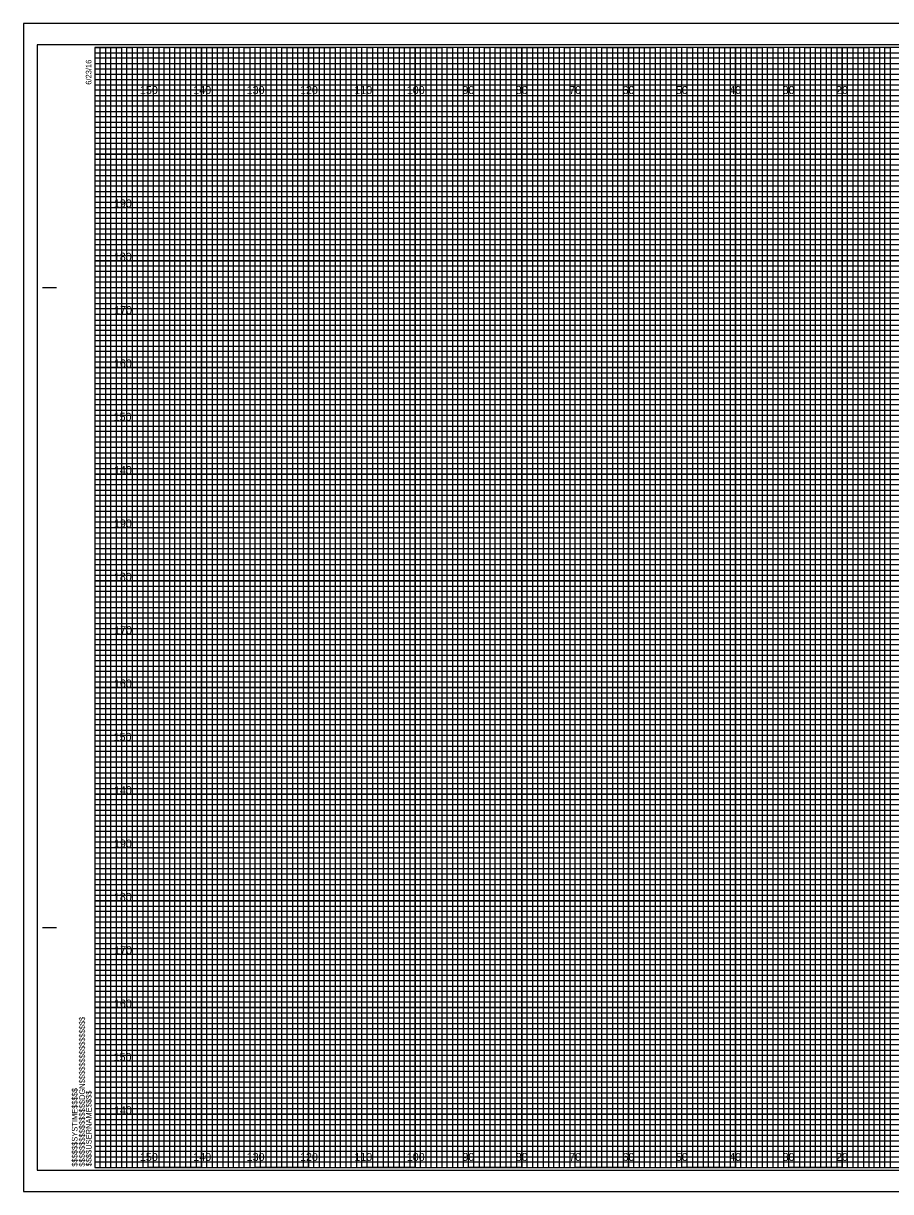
# Model space of a CAD drawing. Extents: x -13 to 323, y -5 to 1754.
# Drawn here: x -13.4 to 149.1, y 215.5 to 434.5 of the extents above; entities that cross this region are included whole.
import ezdxf

# ---------------------------------------------------------------- set-up
doc = ezdxf.new("R2010")
doc.units = 0
for name, color, linetype in [('Exist Cross Section Cell', 7, 'Continuous'), ('Exist XS Center Line Elevation Label', 7, 'Continuous'), ('Exist XS Ground Line', 7, 'Continuous'), ('Prop CMT Pvmt Course 1', 7, 'Continuous'), ('Prop CMT Pvmt Course 2', 7, 'Continuous'), ('Prop CMT Pvmt Course 3', 7, 'Continuous'), ('Prop CMT Shld Paved Course 1', 7, 'Continuous'), ('Prop CMT Shld Paved Course 2', 7, 'Continuous'), ('Prop CMT Subgrade Earthwork', 7, 'Continuous'), ('Prop XS Ditch Standard Text', 7, 'Continuous'), ('Scratch_Level_0', 7, 'Continuous')]:
    doc.layers.add(name, color=color, linetype=linetype)

msp = doc.modelspace()

# ---------------------------------------------------------------- linework, layer by layer
at = {"layer": 'Exist XS Center Line Elevation Label'}
for points in [[(0, 430), (5, 430), (5, 220), (15, 220), (15, 430), (25, 430), (25, 220), (35, 220), (35, 430), (45, 430), (45, 220), (55, 220), (55, 430), (65, 430), (65, 220), (75, 220), (75, 430), (85, 430), (85, 220), (95, 220), (95, 430), (105, 430), (105, 220), (115, 220), (115, 430), (125, 430), (125, 220), (135, 220), (135, 430), (145, 430), (145, 220), (155, 220)], [(0, 425), (275, 425)], [(0, 405), (320, 405), (320, 415), (0, 415)], [(0, 385), (320, 385), (320, 395), (0, 395)], [(0, 365), (320, 365), (320, 375), (0, 375)], [(0, 345), (320, 345), (320, 355), (0, 355)], [(0, 325), (320, 325), (320, 335), (0, 335)], [(0, 305), (320, 305), (320, 315), (0, 315)], [(0, 285), (320, 285), (320, 295), (0, 295)], [(0, 265), (320, 265), (320, 275), (0, 275)], [(0, 245), (320, 245), (320, 255), (0, 255)], [(0, 225), (320, 225), (320, 235), (0, 235)]]:
    msp.add_lwpolyline(points, dxfattribs=at)
at = {"layer": 'Exist XS Ground Line'}
for p, q in [((10, 430), (0, 430)), ((10, 220), (10, 430)), ((30, 430), (20, 430)), ((20, 430), (20, 220)), ((30, 220), (30, 430)), ((50, 430), (40, 430)), ((40, 430), (40, 220)), ((50, 220), (50, 430)), ((70, 430), (60, 430)), ((60, 430), (60, 220)), ((70, 220), (70, 430)), ((90, 430), (80, 430)), ((80, 430), (80, 220)), ((90, 220), (90, 430)), ((110, 430), (100, 430)), ((100, 430), (100, 220)), ((110, 220), (110, 430)), ((130, 430), (120, 430)), ((120, 430), (120, 220)), ((130, 220), (130, 430)), ((150, 430), (140, 430)), ((140, 430), (140, 220)), ((20, 220), (10, 220)), ((40, 220), (30, 220)), ((60, 220), (50, 220)), ((80, 220), (70, 220)), ((100, 220), (90, 220)), ((120, 220), (110, 220)), ((140, 220), (130, 220))]:
    msp.add_line(p, q, dxfattribs=at)
for points in [[(0, 420), (320, 420), (320, 410), (0, 410)], [(0, 400), (320, 400), (320, 390), (0, 390)], [(0, 380), (320, 380), (320, 370), (0, 370)], [(0, 360), (320, 360), (320, 350), (0, 350)], [(0, 340), (320, 340), (320, 330), (0, 330)], [(0, 320), (320, 320), (320, 310), (0, 310)], [(0, 300), (320, 300), (320, 290), (0, 290)], [(0, 280), (320, 280), (320, 270), (0, 270)], [(0, 260), (320, 260), (320, 250), (0, 250)], [(0, 240), (320, 240), (320, 230), (0, 230)]]:
    msp.add_lwpolyline(points, dxfattribs=at)
at = {"layer": 'Prop CMT Pvmt Course 1'}
for p, q in [((323.3, 434.5), (-13.4, 434.5)), ((-13.4, 434.5), (-13.4, 215.5)), ((-13.4, 215.5), (323.3, 215.5))]:
    msp.add_line(p, q, dxfattribs=at)
at = {"layer": 'Prop CMT Pvmt Course 2'}
msp.add_lwpolyline([(-13.4, 215.5), (323.3, 215.5), (323.3, 434.5), (-13.4, 434.5)], close=True, dxfattribs=at)
at = {"layer": 'Prop CMT Pvmt Course 3'}
msp.add_lwpolyline([(-10.8, 219.5), (322.4, 219.5), (322.4, 430.5), (-10.8, 430.5)], close=True, dxfattribs=at)
at = {"layer": 'Prop CMT Shld Paved Course 1'}
for p, q in [((-9.8, 385), (-7.3, 385)), ((-9.7, 385), (-7.2, 385)), ((-9.8, 265), (-7.3, 265)), ((-9.7, 265), (-7.2, 265)), ((0, 220), (0, 220)), ((0, 220), (0, 220)), ((0, 220), (0, 220)), ((0, 220), (0, 220)), ((0, 220), (0, 220)), ((0, 220), (0, 220)), ((0, 220), (0, 220))]:
    msp.add_line(p, q, dxfattribs=at)
msp.add_lwpolyline([(320, 430), (0, 430), (0, 220), (320, 220)], close=True, dxfattribs=at)
at = {"layer": 'Prop CMT Shld Paved Course 2'}
for points in [[(0, 220), (1, 220), (1, 430), (2, 430), (2, 220)], [(2, 220), (3, 220), (3, 430), (4, 430), (4, 220)], [(5, 220), (6, 220), (6, 430), (7, 430), (7, 220)], [(7, 220), (8, 220), (8, 430), (9, 430), (9, 220)], [(10, 220), (11, 220), (11, 430), (12, 430), (12, 220)], [(12, 220), (13, 220), (13, 430), (14, 430), (14, 220)], [(15, 220), (16, 220), (16, 430), (17, 430), (17, 220)], [(17, 220), (18, 220), (18, 430), (19, 430), (19, 220)], [(20, 220), (21, 220), (21, 430), (22, 430), (22, 220)], [(22, 220), (23, 220), (23, 430), (24, 430), (24, 220)], [(25, 220), (26, 220), (26, 430), (27, 430), (27, 220)], [(27, 220), (28, 220), (28, 430), (29, 430), (29, 220)], [(30, 220), (31, 220), (31, 430), (32, 430), (32, 220)], [(32, 220), (33, 220), (33, 430), (34, 430), (34, 220)], [(35, 220), (36, 220), (36, 430), (37, 430), (37, 220)], [(37, 220), (38, 220), (38, 430), (39, 430), (39, 220)], [(40, 220), (41, 220), (41, 430), (42, 430), (42, 220)], [(42, 220), (43, 220), (43, 430), (44, 430), (44, 220)], [(45, 220), (46, 220), (46, 430), (47, 430), (47, 220)], [(47, 220), (48, 220), (48, 430), (49, 430), (49, 220)], [(50, 220), (51, 220), (51, 430), (52, 430), (52, 220)], [(52, 220), (53, 220), (53, 430), (54, 430), (54, 220)], [(55, 220), (56, 220), (56, 430), (57, 430), (57, 220)], [(57, 220), (58, 220), (58, 430), (59, 430), (59, 220)], [(60, 220), (61, 220), (61, 430), (62, 430), (62, 220)], [(62, 220), (63, 220), (63, 430), (64, 430), (64, 220)], [(65, 220), (66, 220), (66, 430), (67, 430), (67, 220)], [(67, 220), (68, 220), (68, 430), (69, 430), (69, 220)], [(70, 220), (71, 220), (71, 430), (72, 430), (72, 220)], [(72, 220), (73, 220), (73, 430), (74, 430), (74, 220)], [(75, 220), (76, 220), (76, 430), (77, 430), (77, 220)], [(77, 220), (78, 220), (78, 430), (79, 430), (79, 220)], [(80, 220), (81, 220), (81, 430), (82, 430), (82, 220)], [(82, 220), (83, 220), (83, 430), (84, 430), (84, 220)], [(85, 220), (86, 220), (86, 430), (87, 430), (87, 220)], [(87, 220), (88, 220), (88, 430), (89, 430), (89, 220)], [(90, 220), (91, 220), (91, 430), (92, 430), (92, 220)], [(92, 220), (93, 220), (93, 430), (94, 430), (94, 220)], [(95, 220), (96, 220), (96, 430), (97, 430), (97, 220)], [(97, 220), (98, 220), (98, 430), (99, 430), (99, 220)], [(100, 220), (101, 220), (101, 430), (102, 430), (102, 220)], [(102, 220), (103, 220), (103, 430), (104, 430), (104, 220)], [(105, 220), (106, 220), (106, 430), (107, 430), (107, 220)], [(107, 220), (108, 220), (108, 430), (109, 430), (109, 220)], [(110, 220), (111, 220), (111, 430), (112, 430), (112, 220)], [(112, 220), (113, 220), (113, 430), (114, 430), (114, 220)], [(115, 220), (116, 220), (116, 430), (117, 430), (117, 220)], [(117, 220), (118, 220), (118, 430), (119, 430), (119, 220)], [(120, 220), (121, 220), (121, 430), (122, 430), (122, 220)], [(122, 220), (123, 220), (123, 430), (124, 430), (124, 220)], [(125, 220), (126, 220), (126, 430), (127, 430), (127, 220)], [(127, 220), (128, 220), (128, 430), (129, 430), (129, 220)], [(130, 220), (131, 220), (131, 430), (132, 430), (132, 220)], [(132, 220), (133, 220), (133, 430), (134, 430), (134, 220)], [(135, 220), (136, 220), (136, 430), (137, 430), (137, 220)], [(137, 220), (138, 220), (138, 430), (139, 430), (139, 220)], [(140, 220), (141, 220), (141, 430), (142, 430), (142, 220)], [(142, 220), (143, 220), (143, 430), (144, 430), (144, 220)], [(145, 220), (146, 220), (146, 430), (147, 430), (147, 220)], [(147, 220), (148, 220), (148, 430), (149, 430), (149, 220)]]:
    msp.add_lwpolyline(points, dxfattribs=at)
at = {"layer": 'Prop CMT Subgrade Earthwork'}
for p, q in [((10, 220), (10, 430)), ((20, 220), (20, 430)), ((30, 220), (30, 430)), ((40, 220), (40, 430)), ((50, 220), (50, 430)), ((60, 220), (60, 430)), ((70, 220), (70, 430)), ((80, 220), (80, 430)), ((90, 220), (90, 430)), ((100, 220), (100, 430)), ((110, 220), (110, 430)), ((120, 220), (120, 430)), ((130, 220), (130, 430)), ((140, 220), (140, 430)), ((0, 420), (320, 420)), ((0, 410), (320, 410)), ((0, 400), (320, 400)), ((0, 390), (320, 390)), ((0, 380), (320, 380)), ((0, 370), (320, 370)), ((0, 360), (320, 360)), ((0, 350), (320, 350)), ((0, 340), (320, 340)), ((0, 330), (320, 330)), ((0, 320), (320, 320)), ((0, 310), (320, 310)), ((0, 300), (320, 300)), ((0, 290), (320, 290)), ((0, 280), (320, 280)), ((0, 270), (320, 270)), ((0, 260), (320, 260)), ((0, 250), (320, 250)), ((0, 240), (320, 240)), ((0, 230), (320, 230))]:
    msp.add_line(p, q, dxfattribs=at)
at = {"layer": 'Scratch_Level_0'}
for p, q in [((0, 429), (260, 429)), ((260, 427.98), (0, 427.98)), ((0, 427.98), (0, 427)), ((0, 427), (260, 427)), ((260, 425.89), (0, 425.89)), ((0, 425.89), (0, 424)), ((0, 424), (320, 424))]:
    msp.add_line(p, q, dxfattribs=at)
for points in [[(0, 423), (270, 423), (320, 423), (320, 422), (0, 422)], [(0, 421), (320, 421), (320, 419), (0, 419)], [(0, 418), (320, 418), (320, 417), (0, 416.98)], [(0, 416), (320, 416), (320, 414), (0, 414)], [(0, 413), (320, 413), (320, 412), (0, 412)], [(0, 411), (320, 411), (320, 409), (0, 409)], [(0, 408), (320, 408), (320, 407), (0, 407)], [(0, 406), (320, 406), (320, 404), (0, 404)], [(0, 403), (320, 403), (320, 402), (0, 402)], [(0, 401), (320, 401), (320, 399), (0, 399)], [(0, 398), (320, 398), (320, 397), (0, 397)], [(0, 396), (320, 396), (320, 393.95), (320, 393), (320, 392), (0, 392)], [(0, 394), (320, 394), (320, 393), (0, 393)], [(0, 391), (320, 391), (320, 389), (0, 389.03)], [(0, 389.03), (320, 389), (320, 388), (0, 388)], [(0, 387), (320, 387), (320, 386), (0, 386)], [(0, 384), (320, 384), (320, 383), (0, 383)], [(0, 382), (320, 382), (320, 381), (0, 381)], [(-0.07, 378.89), (320, 378.89), (320, 377.88), (-0.07, 377.88)], [(0, 377), (320, 377), (320, 376), (0, 376)], [(0, 374), (320, 374), (320, 373), (0, 373)], [(0, 372), (320, 372), (320, 371), (0, 371)], [(0, 369), (320, 369), (320, 368), (0, 368)], [(0, 367), (320, 367), (320, 366), (0, 366)], [(0, 364), (320, 364), (320, 363), (0, 363)], [(0, 362), (320, 362), (320, 361), (0, 361)], [(0, 359), (320, 359), (319.99, 357.98), (0, 358)], [(0, 357), (320, 357), (320, 356), (0, 356)], [(0, 354), (320, 354), (320, 353), (0, 353)], [(0, 352), (320, 352), (320, 351), (0, 351)], [(0, 349), (320, 349), (320, 348), (0, 348)], [(0, 347), (320, 347), (320, 346), (0, 346)], [(0, 344), (320, 344), (320, 343), (0, 343)], [(0, 342), (320, 342), (320, 341), (0, 341)], [(0, 339), (320, 339), (320, 338), (0, 338)], [(0, 336.99), (320.07, 336.91), (320, 336), (0, 336)], [(0, 334), (320, 334), (320, 333), (0, 333)], [(0, 332), (320, 332), (320, 331), (0, 331)], [(0, 329), (320, 329), (320, 328), (0, 328)], [(0, 327), (320, 327), (320, 326), (0, 326)], [(0, 324), (320, 324), (320, 323), (0, 323)], [(0, 322), (320, 322), (320, 321), (0, 321)], [(0, 319), (320, 319), (320, 318), (0, 318)], [(0, 317), (320, 317), (320, 316), (0, 316)], [(0, 314), (320, 314), (320, 313), (0, 313)], [(0, 312), (320, 312), (320, 311), (0, 311)], [(0, 309), (320, 309), (320, 308), (0, 308)], [(0, 307), (320, 307), (320, 306), (0, 306)], [(0, 304), (320, 304), (320, 303), (0, 303)], [(0, 302), (320, 302), (320, 301), (0, 301)], [(0, 299), (320, 299), (319.99, 297.98), (0, 298)], [(0, 297), (320, 297), (320, 296), (0, 296)], [(0, 294), (320, 294), (320, 293), (0, 293)], [(0, 292), (320, 292), (320, 291), (0, 291)], [(0, 289), (320, 289), (320, 288), (0, 288)], [(0, 287), (320, 287), (320, 286), (0, 286)], [(0, 284), (320, 284), (320, 283), (0, 283)], [(0, 282), (320, 282), (320, 281), (0, 281)], [(0, 279), (320, 279), (320, 278), (0, 278)], [(0, 276.99), (320.07, 276.91), (320, 276), (0, 276)], [(0, 274), (320, 274), (320, 273), (0, 273)], [(0, 272), (320, 272), (320, 271), (0, 271)], [(0, 269), (320, 269), (320, 268), (0, 268)], [(0, 267), (320, 267), (320, 266), (0, 266)], [(0, 264), (320, 264), (320, 263), (0, 263)], [(0, 262), (320, 262), (320, 261), (0, 261)], [(0, 259), (320, 259), (320, 258), (0, 258)], [(0, 257), (320, 257), (320, 256), (0, 256)], [(0, 254), (320, 254), (320, 253), (0, 253)], [(0, 252), (320, 252), (320, 251), (0, 251)], [(0, 249), (320, 249), (320, 248), (0, 248)], [(0, 247), (320, 247), (320, 246), (0, 246)], [(0, 244), (320, 244), (320, 243), (0, 243)], [(0, 242), (320, 242), (320, 241), (0, 241)], [(0, 239), (320, 239), (320, 238), (0, 238)], [(0, 237), (320, 237), (320, 236), (0, 236)], [(0, 234), (320, 234), (320, 233), (0, 233)], [(0, 232), (320, 232), (320, 231), (0, 231)], [(0, 229), (320, 229), (320, 228), (0, 228)], [(0, 227), (320, 227), (320, 226), (0, 226)], [(0, 224), (320, 224), (320, 223), (0, 223)], [(0, 222), (320, 222), (320, 221), (0, 221)]]:
    msp.add_lwpolyline(points, dxfattribs=at)

# ---------------------------------------------------------------- texts
at = {"layer": 'Exist Cross Section Cell'}
for s, p in [('190', (3.57, 400)), ('180', (3.55, 390)), ('170', (3.61, 380)), ('160', (3.57, 370)), ('150', (3.52, 360)), ('140', (3.57, 350)), ('190', (3.57, 340)), ('180', (3.55, 330)), ('170', (3.61, 320)), ('160', (3.57, 310)), ('150', (3.52, 300)), ('140', (3.57, 290)), ('190', (3.57, 280)), ('180', (3.55, 270)), ('170', (3.61, 260)), ('160', (3.57, 250)), ('150', (3.52, 240)), ('140', (3.57, 230))]:
    msp.add_text(s, height=1.5, dxfattribs=at).set_placement(p)
at = {"layer": 'Prop CMT Shld Paved Course 1'}
for s, p in [('6/23/16', (-0.65, 423)), ('$$$$$$$$$$$$$$$$DGN$$$$$$$$$$$$$$$$', (-1.88, 220.18)), ('$$$$$$SYSTIME$$$$$', (-3.26, 220.18)), ('$$$$USERNAME$$$$', (-0.62, 220.23))]:
    msp.add_text(s, height=1.05, rotation=90, dxfattribs=at).set_placement(p)
at = {"layer": 'Prop XS Ditch Standard Text'}
for s, p in [('150', (8.44, 421.25)), ('140', (18.44, 421.25)), ('130', (28.44, 421.25)), ('120', (38.44, 421.25)), ('110', (48.62, 421.25)), ('100', (58.44, 421.25)), ('90', (68.86, 421.25)), ('80', (78.86, 421.25)), ('70', (88.86, 421.25)), ('60', (98.86, 421.25)), ('50', (108.86, 421.25)), ('40', (118.86, 421.25)), ('30', (128.86, 421.25)), ('20', (138.86, 421.25)), ('150', (8.44, 221.25)), ('140', (18.44, 221.25)), ('130', (28.44, 221.25)), ('120', (38.44, 221.25)), ('110', (48.62, 221.25)), ('100', (58.44, 221.25)), ('90', (68.86, 221.25)), ('80', (78.86, 221.25)), ('70', (88.86, 221.25)), ('60', (98.86, 221.25)), ('50', (108.86, 221.25)), ('40', (118.86, 221.25)), ('30', (128.86, 221.25)), ('20', (138.86, 221.25))]:
    msp.add_text(s, height=1.5, dxfattribs=at).set_placement(p)

doc.saveas('drawing.dxf')
